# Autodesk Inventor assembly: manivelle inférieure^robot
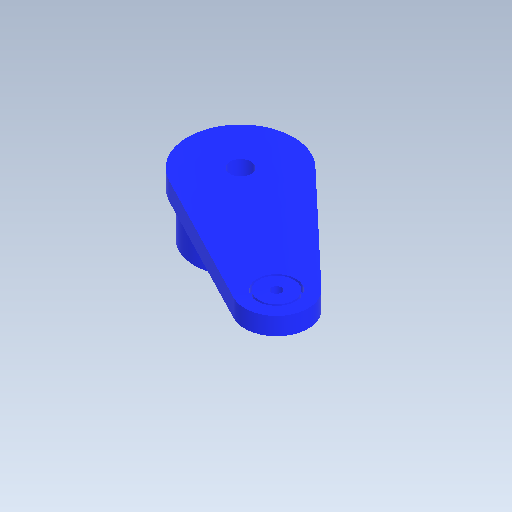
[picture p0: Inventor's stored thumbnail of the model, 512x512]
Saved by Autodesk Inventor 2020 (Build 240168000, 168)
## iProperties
Created: 2018-10
Part Number: manivelle inférieure^robot
Document SubType Name: Assembly
Designer: bruno
Sending System: SolidWorks 2016
Last Author: Prof
Last Saved: 2018-10-03
Author: bruno
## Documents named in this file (4)
- C:\Users\bruno\Documents\Systèmes\Mallette Bras robotisé (273265)\Dossier ressources\Maquette Dobot SW2016\manivelle inférieure^robot.iam
- C:\Users\bruno\Documents\Systèmes\Mallette Bras robotisé (273265)\Dossier ressources\Maquette Dobot SW2016\____230_A.ipt
- C:\Users\bruno\Documents\Systèmes\Mallette Bras robotisé (273265)\Dossier ressources\Maquette Dobot SW2016\MSBS011_A.ipt
- C:\Users\bruno\Documents\Systèmes\Mallette Bras robotisé (273265)\Dossier ressources\Maquette Dobot SW2016\_____32_A.ipt
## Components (6 placed, 3 different names)
1. ____230_A:1
2. MSBS011_A:1
3. MSBS011_A:2
4. MSBS011_A:3
5. MSBS011_A:4
6. _____32_A:1
